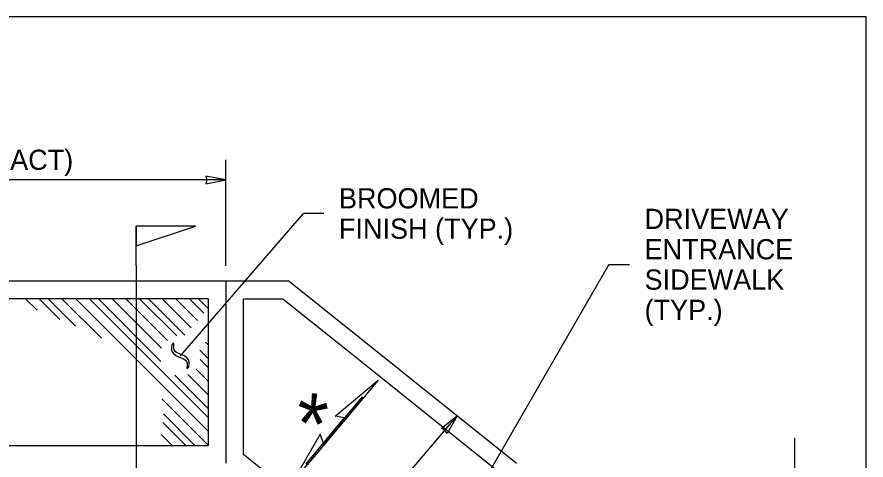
# Model space of a CAD drawing. Extents: x 99862 to 103151, y 100000 to 105076.
# Drawn here: x 102479 to 103151, y 101725 to 102076 of the extents above; entities that cross this region are included whole.
import ezdxf

# ---------------------------------------------------------------- set-up
doc = ezdxf.new("R2010")
doc.units = 0
for name, color, linetype in [('Level 1', 7, 'Continuous'), ('Level 15', 7, 'Continuous'), ('Level 20', 7, 'Continuous'), ('Level 48', 7, 'Continuous'), ('Level 50', 7, 'Continuous'), ('Level 57', 7, 'Continuous'), ('Level 58', 7, 'Continuous'), ('Level 60', 7, 'Continuous'), ('Level 9', 7, 'Continuous')]:
    doc.layers.add(name, color=color, linetype=linetype)

msp = doc.modelspace()

# ---------------------------------------------------------------- linework, layer by layer
at = {"layer": 'Level 1'}
msp.add_lwpolyline([(99862, 99999.5), (103151, 99999.5), (103151, 102075.5), (99862, 102075.5)], close=True, dxfattribs=at)
at = {"layer": 'Level 15'}
for p, q in [((102644.35, 101878.53), (102644.35, 101962.53)), ((102644.35, 101878.53), (102644.35, 101962.53)), ((102608.37, 101807.39), (102705.86, 101920.03)), ((102608.37, 101807.39), (102705.86, 101920.03)), ((102721.86, 101920.03), (102705.86, 101920.03)), ((102721.86, 101920.03), (102705.86, 101920.03)), ((102846.98, 101705.23), (102946.71, 101877.97)), ((102846.98, 101705.23), (102946.71, 101877.97)), ((102946.71, 101877.97), (102947.73, 101879.73)), ((102946.71, 101877.97), (102947.73, 101879.73)), ((102947.73, 101879.73), (102963.73, 101879.73)), ((102947.73, 101879.73), (102963.73, 101879.73)), ((102734.45, 101650.65), (102827.46, 101760.04)), ((102734.45, 101650.65), (102827.46, 101760.04))]:
    msp.add_line(p, q, dxfattribs=at)
for points in [[(102644.35, 101946.53), (102628.63, 101949.61), (102629.35, 101946.53), (102628.63, 101943.44)], [(102644.35, 101946.53), (102628.63, 101949.61), (102629.35, 101946.53), (102628.63, 101943.44)], [(102827.46, 101760.04), (102819.63, 101746.06), (102817.75, 101748.62), (102814.93, 101750.06)], [(102827.46, 101760.04), (102819.63, 101746.06), (102817.75, 101748.62), (102814.93, 101750.06)]]:
    msp.add_lwpolyline(points, close=True, dxfattribs=at)
for points in [[(102644.35, 101946.53), (102140.35, 101946.53)], [(102644.35, 101946.53), (102140.35, 101946.53)], [(103094.35, 101742.53), (103094.35, 101620.01), (103096.44, 101620.01)], [(103094.35, 101742.53), (103094.35, 101620.01), (103096.44, 101620.01)]]:
    msp.add_lwpolyline(points, dxfattribs=at)
at = {"layer": 'Level 20'}
for p, q in [((102573.44, 101878.53), (102573.44, 101794.07)), ((102601.69, 101816.01), (102601.37, 101813.89)), ((102603.27, 101817.41), (102601.69, 101816.01)), ((102603.08, 101813.72), (102603.27, 101817.41)), ((102601.37, 101813.89), (102601.46, 101812.11)), ((102601.46, 101812.11), (102601.96, 101810.57)), ((102601.96, 101810.57), (102602.9, 101809.2)), ((102602.9, 101809.2), (102604.8, 101807.63)), ((102603.47, 101812.12), (102603.08, 101813.72)), ((102604.21, 101810.91), (102603.47, 101812.12)), ((102605.37, 101809.96), (102604.21, 101810.91)), ((102607.6, 101809.01), (102605.37, 101809.96)), ((102611.66, 101807.27), (102607.6, 101809.01)), ((102604.8, 101807.63), (102608.59, 101806.1)), ((102608.59, 101806.1), (102610.93, 101805.08)), ((102610.93, 101805.08), (102612.45, 101803.91)), ((102613.79, 101805.59), (102611.66, 101807.27)), ((102612.45, 101803.91), (102613.19, 101802.8)), ((102613.19, 101802.8), (102613.61, 101801.51)), ((102613.61, 101801.51), (102613.69, 101799.77)), ((102614.78, 101804.13), (102613.79, 101805.59)), ((102615.32, 101802.51), (102614.78, 101804.13)), ((102615.39, 101800.72), (102615.32, 101802.51)), ((102613.69, 101799.77), (102613.43, 101797.36)), ((102613.43, 101797.36), (102615.01, 101798.77)), ((102615.01, 101798.77), (102615.39, 101800.72)), ((102573.44, 101794.07), (102573.44, 101727.38)), ((102573.44, 101794.07), (102573.44, 101717.31))]:
    msp.add_line(p, q, dxfattribs=at)
for points in [[(102707.84, 101721.96), (102738.33, 101758.37), (102730.96, 101759.66), (102764.97, 101788.24), (102708.79, 101721.16)], [(102752.03, 101774.7), (102721.54, 101738.29), (102718.97, 101745.32), (102696.8, 101706.82), (102752.98, 101773.9)]]:
    msp.add_lwpolyline(points, close=True, dxfattribs=at)
at = {"layer": 'Level 48'}
for p, q in [((102630.35, 101852.53), (102392.35, 101852.53)), ((102630.35, 101852.53), (102630.35, 101736.53)), ((102630.35, 101852.53), (102630.35, 101736.53)), ((102658.36, 101852.53), (102689.43, 101852.54)), ((102658.36, 101729.25), (102658.36, 101852.53)), ((102689.43, 101852.54), (102733.72, 101817.11)), ((102733.72, 101817.11), (102758.72, 101797.11)), ((102758.72, 101797.11), (102869.44, 101708.53)), ((102392.35, 101736.53), (102630.35, 101736.53)), ((102392.35, 101736.53), (102630.35, 101736.53)), ((102900.35, 101535.66), (102658.36, 101729.25))]:
    msp.add_line(p, q, dxfattribs=at)
at = {"layer": 'Level 50'}
for p, q in [((102485.86, 101852.53), (102494.96, 101843.43)), ((102485.86, 101852.53), (102494.96, 101843.43)), ((102496.72, 101852.53), (102513, 101836.25)), ((102496.72, 101852.53), (102513, 101836.25)), ((102503.8, 101852.53), (102525.35, 101830.97)), ((102503.8, 101852.53), (102525.35, 101830.97)), ((102514.66, 101852.53), (102545.92, 101821.26)), ((102514.66, 101852.53), (102545.92, 101821.26)), ((102525.52, 101852.53), (102630.35, 101747.69)), ((102525.52, 101852.53), (102630.35, 101747.69)), ((102536.38, 101852.53), (102630.35, 101758.55)), ((102536.38, 101852.53), (102630.35, 101758.55)), ((102543.45, 101852.53), (102592.99, 101802.99)), ((102543.45, 101852.53), (102592.99, 101802.99)), ((102554.31, 101852.53), (102593.51, 101813.33)), ((102554.31, 101852.53), (102593.51, 101813.33)), ((102565.17, 101852.53), (102598.07, 101819.63)), ((102565.17, 101852.53), (102598.07, 101819.63)), ((102576.03, 101852.53), (102605.44, 101823.12)), ((102576.03, 101852.53), (102605.44, 101823.12)), ((102583.1, 101852.53), (102611.92, 101823.71)), ((102583.1, 101852.53), (102611.92, 101823.71)), ((102593.97, 101852.53), (102616.96, 101829.54)), ((102604.83, 101852.53), (102622, 101835.36)), ((102604.83, 101852.53), (102622, 101835.36)), ((102615.69, 101852.53), (102627.04, 101841.18)), ((102615.69, 101852.53), (102627.04, 101841.18)), ((102622.76, 101852.53), (102630.32, 101844.97)), ((102622.76, 101852.53), (102630.32, 101844.97)), ((102628.3, 101818.19), (102630.35, 101816.14)), ((102623.72, 101811.92), (102630.35, 101805.28)), ((102623.72, 101811.92), (102630.35, 101805.28)), ((102624.1, 101804.46), (102630.35, 101798.21)), ((102624.1, 101804.46), (102630.35, 101798.21)), ((102620.61, 101797.09), (102630.35, 101787.35)), ((102620.61, 101797.09), (102630.35, 101787.35)), ((102603.97, 101792), (102630.35, 101765.63)), ((102603.97, 101792), (102630.35, 101765.63)), ((102614.31, 101792.53), (102630.35, 101776.49)), ((102614.31, 101792.53), (102630.35, 101776.49)), ((102593.8, 101773.39), (102630.35, 101736.83)), ((102593.8, 101773.39), (102630.35, 101736.83)), ((102594.89, 101761.43), (102619.8, 101736.53)), ((102594.89, 101761.43), (102619.8, 101736.53)), ((102594.57, 101754.68), (102612.72, 101736.53)), ((102594.57, 101754.68), (102612.72, 101736.53)), ((102593.19, 101745.2), (102601.64, 101736.75)), ((102593.19, 101745.2), (102601.64, 101736.75))]:
    msp.add_line(p, q, dxfattribs=at)
at = {"layer": 'Level 57'}
for q in [(102644.35, 101866.53), (102644.35, 101866.53), (102874.35, 101722.53), (102874.35, 101722.53)]:
    msp.add_line((102694.34, 101866.54), q, dxfattribs=at)
msp.add_lwpolyline([(102644.35, 101866.53), (102392.35, 101866.53)], dxfattribs=at)
msp.add_lwpolyline([(102644.35, 101866.53), (102392.35, 101866.53)], dxfattribs=at)
at = {"layer": 'Level 58'}
msp.add_line((102644.35, 101866.53), (102644.35, 101722.53), dxfattribs=at)
msp.add_line((102644.35, 101866.53), (102644.35, 101722.53), dxfattribs=at)
at = {"layer": 'Level 60'}
msp.add_line((103151, 102075.5), (103151, 102075.5), dxfattribs=at)
at = {"layer": 'Level 9'}
for q in [(102573.44, 101910.05), (102573.44, 101910.05), (102573.44, 101794.07)]:
    msp.add_line((102573.44, 101878.53), q, dxfattribs=at)
msp.add_lwpolyline([(102573.44, 101894.53), (102620.32, 101910.05), (102573.44, 101910.05)], close=True, dxfattribs=at)
msp.add_lwpolyline([(102573.44, 101894.53), (102620.32, 101910.05), (102573.44, 101910.05)], close=True, dxfattribs=at)

# ---------------------------------------------------------------- texts
at = {"layer": 'Level 20'}
for s, p in [('VARIES (SEE CONTRACT)', (102257.28, 101954.53)), ('DRIVEWAY', (102975.73, 101907.74)), ('ENTRANCE', (102975.73, 101883.74)), ('SIDEWALK', (102975.73, 101859.74)), ('(TYP.)', (102975.73, 101835.74))]:
    msp.add_text(s, height=16, dxfattribs=at).set_placement(p)
for s, height, rotation, p in [('BROOMED', 16, 360, (102733.86, 101924.03)), ('FINISH (TYP.)', 16, 360, (102733.86, 101900.03)), ('*', 48, 354.80672, (102697.72, 101731))]:
    msp.add_text(s, height=height, rotation=rotation, dxfattribs=at).set_placement(p)

doc.saveas('drawing.dxf')
